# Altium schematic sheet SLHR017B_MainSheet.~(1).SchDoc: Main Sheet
size 431 x 279 mm; Date: Not shown in title block; ApprovedBy: Not shown in title block; CheckedBy: Not shown in title block; Author: Not shown in title block; CompanyName: Not shown in title block; DrawnBy: Kirby Kruckmeyer; Engineer: Not shown in title block; Organization: Not shown in title block; Address1: Not shown in title block; Address2: Not shown in title block; Address3: Not shown in title block; Address4: Not shown in title block; DocumentNumber: 1; Revision: Use project parameter SCH_Rev; SheetNumber: 1; SheetTotal: 2; PageSetup: Record=PageOptions¦CenterHorizontal=True¦CenterVertical=True¦PrintScale=1.00¦XCorrection=1.00¦YCorrection=1.00¦PrintKind=0¦BorderSize=5000000¦LeftOffset=0¦BottomOffset=0¦Orientation=2¦PaperLength=1000¦PaperWidth=1000¦Scale=100¦PaperSource=15¦PrintQuality=600¦MediaType=1¦DitherType=10¦PaperKind=Letter¦PrintScaleMode=1
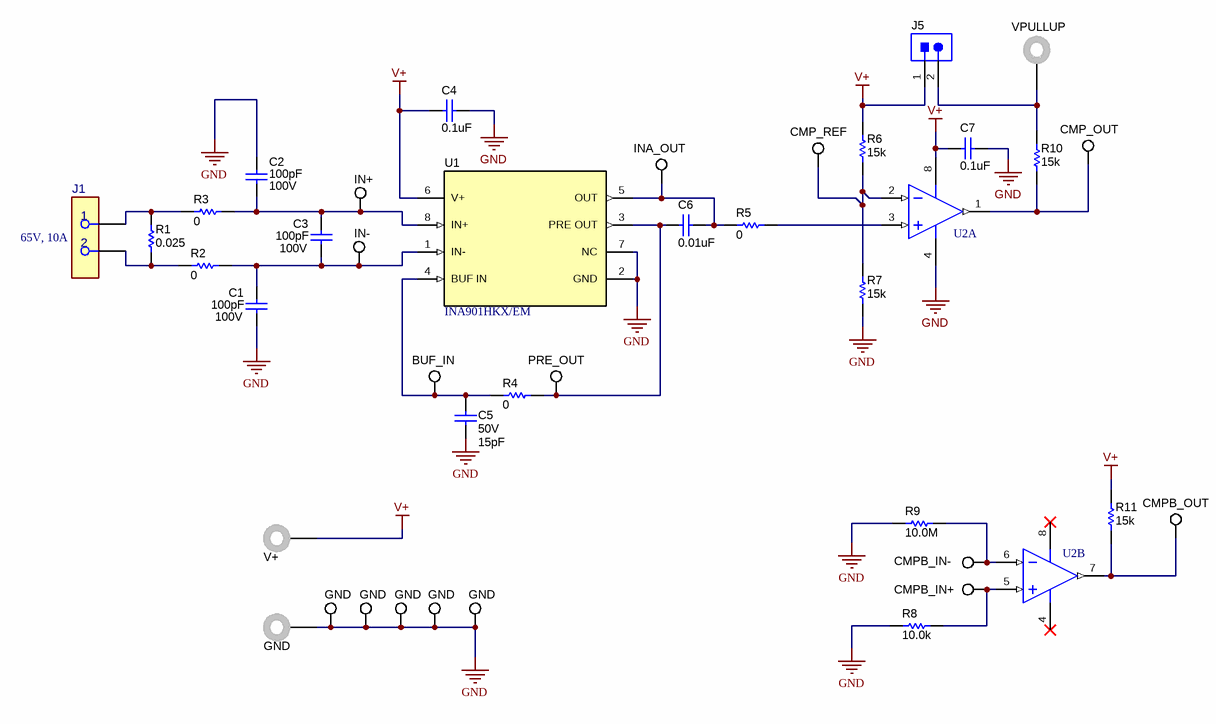
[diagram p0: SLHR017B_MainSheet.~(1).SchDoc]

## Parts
C1  Cap_F: 100pF  VDC_V: 100V  [0805_HV]  (hidden comment: C0805C101J1RACTU)
C2  Cap_F: 100pF  VDC_V: 100V  [0805_HV]  (hidden comment: C0805C101J1RACTU)
C3  Cap_F: 100pF  VDC_V: 100V  [0805_HV]  (hidden comment: C0805C101J1RACTU)
C4  ValueDisplayed: 0.1uF  [0805_HV]  (hidden comment: C0805C104K1RACTU)
C5  VDC_V: 50V  ValueDisplayed: 15pF  [0805_HV]  (hidden comment: VJ0805A150JXACW1BC)
C6  ValueDisplayed: 0.01uF  [0805_HV]  (hidden comment: C0805C103F1GACTU)
C7  ValueDisplayed: 0.1uF  [0805_HV]  (hidden comment: C0805C104K1RACTU)
J1  691137710002  [FP-691137710002_HDR2-MFG]  (value not drawn)
J2  V+  [Keystone_575-4]
J3  GND  [Keystone_575-4]
J5  PBC02SAAN  [Sullins_PBC02SAAN]  (value not drawn)
J6  VPULLUP  [Keystone_575-4]
R1  ValueDisplayed: 0.025  [2512]  (hidden comment: CRA2512-FZ-R025ELF)
R2  ValueDisplayed: 0  [0805_HV]  (hidden comment: ERJ-6GEY0R00V)
R3  ValueDisplayed: 0  [0805_HV]  (hidden comment: ERJ-6GEY0R00V)
R4  ValueDisplayed: 0  [0805_HV]  (hidden comment: ERJ-6GEY0R00V)
R5  ValueDisplayed: 0  [0805_HV]  (hidden comment: ERJ-6GEY0R00V)
R6  ValueDisplayed: 15k  [0805_HV]  (hidden comment: ERJ-6GEYJ153V)
R7  ValueDisplayed: 15k  [0805_HV]  (hidden comment: ERJ-6GEYJ153V)
R8  ValueDisplayed: 10.0k  [0805_HV]  (hidden comment: RNCP0805FTD10K0)
R9  ValueDisplayed: 10.0M  [0805_HV]  (hidden comment: CRCW080510M0FKEA)
R10  ValueDisplayed: 15k  [0805_HV]  (hidden comment: ERJ-6GEYJ153V)
R11  ValueDisplayed: 15k  [0805_HV]  (hidden comment: ERJ-6GEYJ153V)
TP1  GND  [Testpoint_Keystone_Miniature]
TP2  IN+  [Testpoint_Keystone_Miniature]
TP3  IN-  [Testpoint_Keystone_Miniature]
TP4  GND  [Testpoint_Keystone_Miniature]
TP5  GND  [Testpoint_Keystone_Miniature]
TP6  BUF_IN  [Testpoint_Keystone_Miniature]
TP7  GND  [Testpoint_Keystone_Miniature]
TP8  PRE_OUT  [Testpoint_Keystone_Miniature]
TP9  INA_OUT  [Testpoint_Keystone_Miniature]
TP10  CMP_REF  [Testpoint_Keystone_Miniature]
TP11  CMPB_IN-  [Testpoint_Keystone_Miniature]
TP12  CMPB_IN+  [Testpoint_Keystone_Miniature]
TP13  CMP_OUT  [Testpoint_Keystone_Miniature]
TP14  CMPB_OUT  [Testpoint_Keystone_Miniature]
TP15  GND  [Testpoint_Keystone_Miniature]
U1  INA901HKX/EM  [HKX0008A_Custom_B]
U2  LM193AJRLQMLV  [NAB0008A]  (value not drawn)  (parts A,B of 2)

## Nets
GND: C1.2 C2.1 C4.2 C5.2 C7.2 J3.1 R7.1 R8.1 R9.1 TP1.1 TP4.1 TP5.1 TP7.1 TP15.1 U1.2(GND) U1.7(NC) U2.4(GND)
V+: C4.1 C7.1 J2.1 J5.1 R6.2 R11.2 U1.6(V+) U2.8(V+)
NetC1_1: C1.1 C3.2 R2.2 TP3.1 U1.1(IN-)
NetC2_2: C2.2 C3.1 R3.2 TP2.1 U1.8(IN+)
NetC5_1: C5.1 R4.1 TP6.1 U1.4(BUF_IN)
NetC6_1: C6.1 R4.2 TP8.1 U1.3(PRE_OUT)
NetC6_2: C6.2 R5.1 TP9.1 U1.5(OUT)
NetJ1_1: J1.1 R1.2 R3.1
NetJ1_2: J1.2 R1.1 R2.1
NetJ5_2: J5.2 J6.1 R10.2
NetR5_2: R5.2 U2.3(INA+)
NetR6_1: R6.1 R7.2 TP10.1 U2.2(INA-)
NetR8_2: R8.2 TP12.1 U2.5(INB+)
NetR9_2: R9.2 TP11.1 U2.6(INB-)
NetR10_1: R10.1 TP13.1 U2.1(OUTA)
NetR11_1: R11.1 TP14.1 U2.7(OUTB)

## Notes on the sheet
- (near J1) 65V, 10A

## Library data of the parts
C1-C3 = CMP-0007706-2: CAP, CERM, 100 pF, 100 V, +/- 5%, X7R, 0805; Manufacturer: Kemet; TaMin_C: -55°C; Polarized: N; SizeAreaWB_mm2: 6.75; Value1: Unknown; U/M: EA; Value: 100pF; TaMax_C: 125°C; SizeZ_mm: 1.45; SizeX_mm: 2; SizeY_mm: 1.25; Cap_Case: 0805; SizeArea_mm2: 2.5; AEC Category: Q200
C4 C7 = CMP-0007722-2: CAP, CERM, 0.1 uF, 100 V, +/- 10%, X7R, 0805; Manufacturer: Kemet; TaMin_C: -55°C; ESR_ohm: 0.064; Polarized: N; SizeAreaWB_mm2: 6.75; Value1: 0.064 ohm; U/M: EA; Value: 0.1uF; TaMax_C: 125°C; SizeZ_mm: 1.45; SizeX_mm: 2; SizeY_mm: 1.25; Cap_Case: 0805; Value2: 100V; SizeArea_mm2: 2.5; Cap_F: 100nF; IRMS_A: 1.64A; AEC Category: Q200
C5 = CMP-0008431-2: CAP, CERM, 15 pF, 50 V, +/- 5%, C0G/NP0, 0805; Manufacturer: Vishay-Bccomponents; TaMin_C: -55°C; Polarized: N; SizeAreaWB_mm2: 6.75; Value1: Unknown; U/M: EA; Value: 15pF; TaMax_C: 125°C; SizeZ_mm: 1.45; SizeX_mm: 2; SizeY_mm: 1.25; Cap_Case: 0805; SizeArea_mm2: 2.5; AEC Category: Q200
C6 = CMP-0007716-2: CAP, CERM, 0.01 uF, 100 V, +/- 1%, C0G/NP0, 0805; Manufacturer: Kemet; TaMin_C: -55°C; Polarized: N; SizeAreaWB_mm2: 6.75; Value1: Unknown; U/M: EA; Value: 0.01uF; TaMax_C: 125°C; SizeZ_mm: 1.45; SizeX_mm: 2; SizeY_mm: 1.25; Cap_Case: 0805; Value2: 100V; SizeArea_mm2: 2.5; Cap_F: 10nF; AEC Category: Q200
J1 = CMP-0087503-1: TERM BLK 2POS SIDE ENTRY 5MM PCB; Manufacturer: Würth Elektronik; Symbol Name: SYM-691137710002; Row_Count: 1; Current_A: 16A; ContactFinish: Tin,Nickel; Voltage_V: 300V
J2 J3 J6 = CMP-0055165-2: Standard Banana Jack, Uninsulated, 5.5mm; Manufacturer: Keystone; PartNumber: 575-4; CT: TRUE; Green_REACh: Passed; CNHeader: FALSE; Green_Lifecycle: Active
J5 = CMP-0054566-1: Header, 100mil, 2x1, Gold, TH; Manufacturer: Sullins Connector Solutions; CNHeader: TRUE; Current_A: 3A; Green_Lifecycle: Active; Shrouded: N; Gender: Male; Green_REACh: Passed; Voltage_V: 1.8kV; Row_Count: 1; Pitch_mm: 2.54; CT: FALSE; Cert_UL: Y
R1 = CMP-0015421-2: RES, 0.025, 1%, 3 W, 2512; Manufacturer: Bourns; Power_W: 3W; TempCo: 75 ppm/C; Value_Code: R025; U/M: EA; Value: 0.025; EIA_Code: E96; SizeX_mm: 6.3; SizeY_mm: 3.2; SizeZ_mm: 0.71; SizeArea_mm2: 20.16; VDC_V: 0V; AEC Category: Q200
R2-R5 = CMP-0020616-3: RES, 0, 5%, 0.125 W, AEC-Q200 Grade 0, 0805; Manufacturer: Panasonic; Power_W: 125mW; TempCo: 600 ppm/C; Value_Code: 0000; Value: 0; EIA_Code: E24; SizeX_mm: 2; SizeY_mm: 1.25; SizeZ_mm: 1.45; Value2: 0.125W; SizeArea_mm2: 2.5; AEC Qualified: Y; VDC_V: 150V; AEC Category: Q200; SizeAreaWB_mm2: 6.75
R6 R7 R10 R11 = CMP-0020646-3: RES, 15 k, 5%, 0.125 W, AEC-Q200 Grade 0, 0805; Manufacturer: Panasonic; Power_W: 125mW; TempCo: 200 ppm/C; Value_Code: 15k0; Value: 15k; EIA_Code: E24; SizeX_mm: 2; SizeY_mm: 1.25; SizeZ_mm: 1.45; Value2: 0.125W; SizeArea_mm2: 2.5; AEC Qualified: Y; VDC_V: 150V; AEC Category: Q200; AEC Grade: 0; SizeAreaWB_mm2: 6.75
R8 = CMP-0084247-1: RES, 10.0 k, 1%, 0.25 W, AEC-Q200 Grade 0, 0805; Manufacturer: Stackpole Electronics Inc; Power_W: 250mW; Green_Lifecycle: Active; TempCo: 100 ppm/C; SizeAreaWB_mm2: 6.75; Value_Code: 10k0; Green_REACh: Passed; Value: 10.0k; EIA_Code: E96; Res_ohm: 10k; SizeX_mm: 2; SizeY_mm: 1.25; SizeZ_mm: 1.45; Value2: 0.25W; SizeArea_mm2: 2.5; AEC Qualified: Y; AEC Grade: 0; AEC Category: Q200
R9 = CMP-0020846-3: RES, 10.0 M, 1%, 0.125 W, AEC-Q200 Grade 0, 0805; Manufacturer: Vishay-Dale; Power_W: 125mW; TempCo: 100 ppm/C; Value_Code: 10M0; Value: 10.0Meg; EIA_Code: E96; Res_ohm: 10M; SizeX_mm: 2; SizeY_mm: 1.25; SizeZ_mm: 1.45; Value2: 0.125W; SizeArea_mm2: 2.5; AEC Qualified: Y; VDC_V: 150V; AEC Category: Q200; AEC Grade: 0
TP1-TP15 = CMP-0055152-1: Test Point, Miniature, SMT; Manufacturer: Keystone; CNHeader: FALSE; Green_Lifecycle: Active; Green_REACh: Passed; CT: TRUE
U1 = CMP-0081563-2: Voltage Output, Unidirectional Measurement Current-Shunt Monitor, HKX0008A (CFP-8); Manufacturer: Texas Instruments; SizeZ_mm: 2.8; Rating: Space; AEC Category: Q200; CompType: IC; AEC Qualified: N
U2 = CMP-0067897-1: Low Power Low Offset Voltage Dual Comparator, 8-pin CerDIP; Manufacturer: Texas Instruments; High-Reliability: Y; CompType: Amplifiers; PackageTopMarking: NSZSSXXYYA*LM193AJRLV Q*5962R*9452603VPA; PowerWise: N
